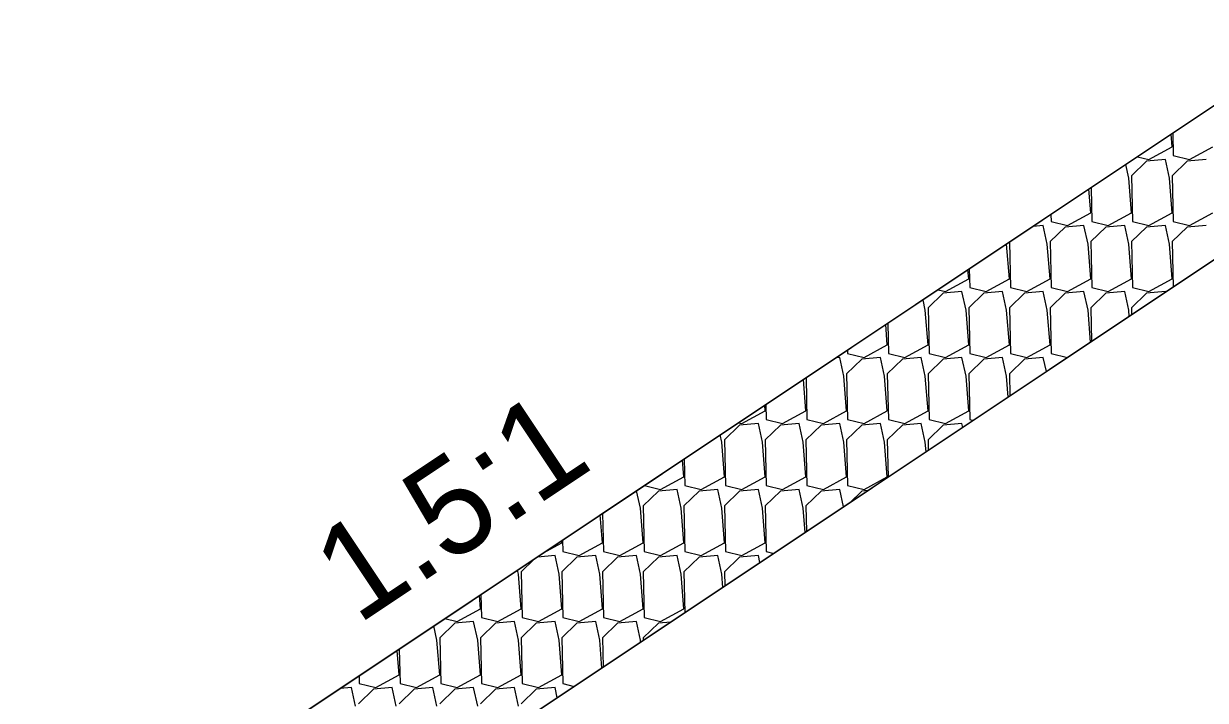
# Model space of a CAD drawing. Extents: x -26 to 4903, y -1010 to 9587.
# Drawn here: x 86.01 to 104.45, y 5010.51 to 5021.07 of the extents above; entities that cross this region are included whole.
import ezdxf

# ---------------------------------------------------------------- set-up
doc = ezdxf.new("R2010")
doc.units = 0
for name, color, linetype in [('Default', 7, 'Continuous'), ('Prop CMT Slope Grass', 7, 'Continuous'), ('Prop XS Class II Rip Rap Ditch Liner', 7, 'Continuous'), ('Prop XS Earthwork Shape', 7, 'Continuous'), ('Prop XS Side Slope Text', 7, 'Continuous')]:
    doc.layers.add(name, color=color, linetype=linetype)

msp = doc.modelspace()

# ---------------------------------------------------------------- linework, layer by layer
at = {"layer": 'Default'}
msp.add_line((106.5, 5021.066), (77.043, 5001.428), dxfattribs=at)
at = {"layer": 'Prop CMT Slope Grass'}
msp.add_line((110.001, 5020.996), (86.006, 5005), dxfattribs=at)
at = {"layer": 'Prop XS Class II Rip Rap Ditch Liner'}
for p, q in [((77.043, 5001.428), (106.5, 5021.066)), ((103.928, 5019.145), (103.912, 5019.341)), ((103.936, 5019.357), (103.943, 5019.011)), ((103.564, 5018.947), (103.928, 5019.145)), ((104.199, 5018.947), (104.563, 5019.145)), ((103.529, 5018.924), (103.293, 5018.695)), ((103.387, 5018.991), (103.564, 5018.947)), ((103.822, 5018.947), (103.529, 5018.924)), ((103.885, 5018.657), (103.822, 5018.947)), ((104.164, 5018.924), (103.928, 5018.695)), ((103.943, 5019.011), (104.199, 5018.947)), ((104.457, 5018.947), (104.164, 5018.924)), ((103.25, 5018.657), (103.204, 5018.869)), ((103.293, 5018.115), (103.25, 5018.657)), ((103.293, 5018.695), (103.308, 5017.982)), ((103.928, 5018.115), (103.885, 5018.657)), ((103.928, 5018.695), (103.943, 5017.982)), ((102.658, 5018.115), (102.629, 5018.486)), ((102.662, 5018.508), (102.673, 5017.982)), ((102.036, 5018.091), (102.038, 5017.982)), ((102.038, 5017.982), (102.294, 5017.917)), ((102.294, 5017.917), (102.658, 5018.115)), ((102.673, 5017.982), (102.929, 5017.917)), ((102.929, 5017.917), (103.293, 5018.115)), ((103.308, 5017.982), (103.564, 5017.917)), ((103.564, 5017.917), (103.928, 5018.115)), ((103.943, 5017.982), (104.199, 5017.917)), ((104.199, 5017.917), (104.563, 5018.115)), ((101.917, 5017.917), (101.757, 5017.905)), ((101.98, 5017.628), (101.917, 5017.917)), ((102.259, 5017.894), (102.023, 5017.666)), ((102.552, 5017.917), (102.259, 5017.894)), ((102.615, 5017.628), (102.552, 5017.917)), ((102.894, 5017.894), (102.658, 5017.666)), ((103.187, 5017.917), (102.894, 5017.894)), ((103.25, 5017.628), (103.187, 5017.917)), ((103.529, 5017.894), (103.293, 5017.666)), ((103.822, 5017.917), (103.529, 5017.894)), ((103.885, 5017.628), (103.822, 5017.917)), ((104.164, 5017.894), (103.928, 5017.666)), ((104.457, 5017.917), (104.164, 5017.894)), ((101.345, 5017.628), (101.345, 5017.63)), ((101.388, 5017.086), (101.345, 5017.628)), ((101.388, 5017.659), (101.403, 5016.952)), ((102.023, 5017.086), (101.98, 5017.628)), ((102.023, 5017.666), (102.038, 5016.952)), ((102.658, 5017.086), (102.615, 5017.628)), ((102.658, 5017.666), (102.673, 5016.952)), ((103.293, 5017.086), (103.25, 5017.628)), ((103.293, 5017.666), (103.308, 5016.952)), ((103.928, 5017.086), (103.885, 5017.628)), ((103.928, 5017.666), (103.943, 5016.958)), ((100.753, 5017.086), (100.742, 5017.228)), ((100.762, 5017.241), (100.769, 5016.952)), ((100.389, 5016.888), (100.753, 5017.086)), ((101.024, 5016.888), (101.388, 5017.086)), ((101.659, 5016.888), (102.023, 5017.086)), ((102.294, 5016.888), (102.658, 5017.086)), ((102.929, 5016.888), (103.293, 5017.086)), ((103.564, 5016.888), (103.928, 5017.086)), ((100.354, 5016.865), (100.118, 5016.636)), ((100.275, 5016.916), (100.389, 5016.888)), ((100.647, 5016.888), (100.354, 5016.865)), ((100.711, 5016.598), (100.647, 5016.888)), ((100.989, 5016.865), (100.753, 5016.636)), ((100.769, 5016.952), (101.024, 5016.888)), ((101.282, 5016.888), (100.989, 5016.865)), ((101.345, 5016.598), (101.282, 5016.888)), ((101.624, 5016.865), (101.388, 5016.636)), ((101.403, 5016.952), (101.659, 5016.888)), ((101.917, 5016.888), (101.624, 5016.865)), ((101.98, 5016.598), (101.917, 5016.888)), ((102.259, 5016.865), (102.023, 5016.636)), ((102.038, 5016.952), (102.294, 5016.888)), ((102.552, 5016.888), (102.259, 5016.865)), ((102.615, 5016.598), (102.552, 5016.888)), ((102.894, 5016.865), (102.658, 5016.636)), ((102.673, 5016.952), (102.929, 5016.888)), ((103.187, 5016.888), (102.894, 5016.865)), ((103.25, 5016.598), (103.187, 5016.888)), ((103.529, 5016.865), (103.293, 5016.636)), ((103.308, 5016.952), (103.564, 5016.888)), ((103.822, 5016.888), (103.529, 5016.865)), ((103.824, 5016.879), (103.822, 5016.888)), ((100.076, 5016.598), (100.04, 5016.76)), ((100.118, 5016.056), (100.076, 5016.598)), ((100.118, 5016.636), (100.134, 5015.923)), ((100.753, 5016.056), (100.711, 5016.598)), ((100.753, 5016.636), (100.769, 5015.923)), ((101.388, 5016.056), (101.345, 5016.598)), ((101.388, 5016.636), (101.403, 5015.923)), ((102.023, 5016.056), (101.98, 5016.598)), ((102.023, 5016.636), (102.038, 5015.923)), ((102.655, 5016.099), (102.615, 5016.598)), ((102.658, 5016.636), (102.669, 5016.109)), ((103.258, 5016.501), (103.25, 5016.598)), ((103.293, 5016.636), (103.295, 5016.526)), ((99.483, 5016.056), (99.458, 5016.372)), ((99.489, 5016.392), (99.499, 5015.923)), ((98.863, 5015.975), (98.864, 5015.923)), ((99.12, 5015.858), (99.483, 5016.056)), ((99.754, 5015.858), (100.118, 5016.056)), ((100.389, 5015.858), (100.753, 5016.056)), ((101.024, 5015.858), (101.388, 5016.056)), ((101.659, 5015.858), (102.023, 5016.056)), ((98.742, 5015.858), (98.68, 5015.853)), ((98.806, 5015.568), (98.742, 5015.858)), ((99.084, 5015.835), (98.848, 5015.606)), ((98.864, 5015.923), (99.12, 5015.858)), ((99.377, 5015.858), (99.084, 5015.835)), ((99.441, 5015.568), (99.377, 5015.858)), ((99.719, 5015.835), (99.483, 5015.606)), ((99.499, 5015.923), (99.754, 5015.858)), ((100.012, 5015.858), (99.719, 5015.835)), ((100.076, 5015.568), (100.012, 5015.858)), ((100.354, 5015.835), (100.118, 5015.606)), ((100.134, 5015.923), (100.389, 5015.858)), ((100.647, 5015.858), (100.354, 5015.835)), ((100.711, 5015.568), (100.647, 5015.858)), ((100.989, 5015.835), (100.753, 5015.606)), ((100.769, 5015.923), (101.024, 5015.858)), ((101.282, 5015.858), (100.989, 5015.835)), ((101.345, 5015.568), (101.282, 5015.858)), ((101.624, 5015.835), (101.388, 5015.606)), ((101.403, 5015.923), (101.659, 5015.858)), ((101.917, 5015.858), (101.624, 5015.835)), ((101.965, 5015.639), (101.917, 5015.858)), ((102.038, 5015.923), (102.293, 5015.858)), ((98.848, 5015.026), (98.806, 5015.568)), ((98.848, 5015.606), (98.864, 5014.893)), ((99.483, 5015.026), (99.441, 5015.568)), ((99.483, 5015.606), (99.499, 5014.893)), ((100.118, 5015.026), (100.076, 5015.568)), ((100.118, 5015.606), (100.134, 5014.893)), ((100.753, 5015.026), (100.711, 5015.568)), ((100.753, 5015.606), (100.769, 5014.893)), ((101.371, 5015.243), (101.345, 5015.568)), ((101.388, 5015.606), (101.396, 5015.26)), ((98.213, 5015.026), (98.175, 5015.516)), ((98.215, 5015.543), (98.229, 5014.893)), ((97.215, 5014.828), (97.578, 5015.026)), ((97.578, 5015.026), (97.572, 5015.114)), ((97.589, 5015.126), (97.594, 5014.893)), ((97.85, 5014.828), (98.213, 5015.026)), ((98.485, 5014.828), (98.848, 5015.026)), ((99.12, 5014.828), (99.483, 5015.026)), ((99.754, 5014.828), (100.118, 5015.026)), ((100.389, 5014.828), (100.753, 5015.026)), ((97.163, 5014.842), (97.215, 5014.828)), ((97.472, 5014.828), (97.179, 5014.805)), ((97.536, 5014.539), (97.472, 5014.828)), ((97.594, 5014.893), (97.85, 5014.828)), ((98.107, 5014.828), (97.814, 5014.805)), ((98.171, 5014.539), (98.107, 5014.828)), ((98.229, 5014.893), (98.485, 5014.828)), ((98.742, 5014.828), (98.449, 5014.805)), ((98.806, 5014.539), (98.742, 5014.828)), ((98.864, 5014.893), (99.12, 5014.828)), ((99.377, 5014.828), (99.084, 5014.805)), ((99.441, 5014.539), (99.377, 5014.828)), ((99.499, 5014.893), (99.754, 5014.828)), ((100.012, 5014.828), (99.719, 5014.805)), ((100.076, 5014.539), (100.012, 5014.828)), ((100.134, 5014.893), (100.389, 5014.828)), ((100.647, 5014.828), (100.354, 5014.805)), ((100.66, 5014.769), (100.647, 5014.828)), ((100.769, 5014.893), (100.824, 5014.879)), ((96.901, 5014.539), (96.876, 5014.651)), ((97.179, 5014.805), (96.944, 5014.577)), ((97.814, 5014.805), (97.578, 5014.577)), ((98.449, 5014.805), (98.213, 5014.577)), ((99.084, 5014.805), (98.848, 5014.577)), ((99.719, 5014.805), (99.483, 5014.577)), ((100.354, 5014.805), (100.118, 5014.577)), ((96.944, 5013.997), (96.901, 5014.539)), ((96.944, 5014.577), (96.959, 5013.863)), ((97.578, 5013.997), (97.536, 5014.539)), ((97.578, 5014.577), (97.594, 5013.863)), ((98.213, 5013.997), (98.171, 5014.539)), ((98.213, 5014.577), (98.229, 5013.863)), ((98.848, 5013.997), (98.806, 5014.539)), ((98.848, 5014.577), (98.864, 5013.863)), ((99.483, 5013.997), (99.441, 5014.539)), ((99.483, 5014.577), (99.496, 5013.993)), ((100.087, 5014.388), (100.076, 5014.539)), ((100.118, 5014.577), (100.122, 5014.411)), ((96.315, 5014.277), (96.324, 5013.863)), ((96.309, 5013.997), (96.288, 5014.258)), ((95.945, 5013.799), (96.309, 5013.997)), ((96.58, 5013.799), (96.944, 5013.997)), ((97.215, 5013.799), (97.578, 5013.997)), ((97.85, 5013.799), (98.213, 5013.997)), ((98.485, 5013.799), (98.848, 5013.997)), ((99.12, 5013.799), (99.483, 5013.997)), ((95.631, 5013.509), (95.571, 5013.781)), ((95.91, 5013.776), (95.674, 5013.547)), ((95.694, 5013.862), (95.945, 5013.799)), ((96.202, 5013.799), (95.91, 5013.776)), ((96.266, 5013.509), (96.202, 5013.799)), ((96.545, 5013.776), (96.309, 5013.547)), ((96.324, 5013.863), (96.58, 5013.799)), ((96.837, 5013.799), (96.545, 5013.776)), ((96.901, 5013.509), (96.837, 5013.799)), ((97.179, 5013.776), (96.944, 5013.547)), ((96.959, 5013.863), (97.215, 5013.799)), ((97.472, 5013.799), (97.179, 5013.776)), ((97.536, 5013.509), (97.472, 5013.799)), ((97.814, 5013.776), (97.578, 5013.547)), ((97.594, 5013.863), (97.85, 5013.799)), ((98.107, 5013.799), (97.814, 5013.776)), ((98.171, 5013.509), (98.107, 5013.799)), ((98.449, 5013.776), (98.213, 5013.547)), ((98.229, 5013.863), (98.485, 5013.799)), ((98.742, 5013.799), (98.449, 5013.776)), ((98.801, 5013.53), (98.742, 5013.799)), ((98.864, 5013.863), (99.12, 5013.799)), ((99.084, 5013.776), (98.896, 5013.594)), ((99.181, 5013.783), (99.084, 5013.776)), ((95.674, 5013.547), (95.689, 5012.834)), ((96.309, 5013.547), (96.324, 5012.834)), ((96.944, 5013.547), (96.959, 5012.834)), ((97.578, 5013.547), (97.594, 5012.834)), ((98.213, 5013.547), (98.222, 5013.144)), ((95.039, 5012.967), (95.004, 5013.403)), ((95.041, 5013.427), (95.054, 5012.834)), ((95.674, 5012.967), (95.631, 5013.509)), ((96.309, 5012.967), (96.266, 5013.509)), ((96.944, 5012.967), (96.901, 5013.509)), ((97.578, 5012.967), (97.536, 5013.509)), ((98.201, 5013.13), (98.171, 5013.509)), ((94.404, 5012.967), (94.401, 5013.001)), ((94.415, 5013.01), (94.419, 5012.834)), ((94.116, 5012.811), (94.404, 5012.967)), ((94.419, 5012.834), (94.675, 5012.769)), ((94.675, 5012.769), (95.039, 5012.967)), ((95.054, 5012.834), (95.31, 5012.769)), ((95.31, 5012.769), (95.674, 5012.967)), ((95.689, 5012.834), (95.945, 5012.769)), ((95.945, 5012.769), (96.309, 5012.967)), ((96.324, 5012.834), (96.58, 5012.769)), ((96.58, 5012.769), (96.944, 5012.967)), ((96.959, 5012.834), (97.215, 5012.769)), ((97.215, 5012.769), (97.578, 5012.967)), ((97.594, 5012.834), (97.712, 5012.804)), ((93.972, 5012.715), (93.769, 5012.518)), ((94.298, 5012.769), (94.022, 5012.747)), ((94.361, 5012.48), (94.298, 5012.769)), ((94.64, 5012.746), (94.404, 5012.518)), ((94.933, 5012.769), (94.64, 5012.746)), ((94.996, 5012.48), (94.933, 5012.769)), ((95.275, 5012.746), (95.039, 5012.518)), ((95.568, 5012.769), (95.275, 5012.746)), ((95.631, 5012.48), (95.568, 5012.769)), ((95.91, 5012.746), (95.674, 5012.518)), ((96.202, 5012.769), (95.91, 5012.746)), ((96.266, 5012.48), (96.202, 5012.769)), ((96.545, 5012.746), (96.309, 5012.518)), ((96.837, 5012.769), (96.545, 5012.746)), ((96.901, 5012.48), (96.837, 5012.769)), ((97.179, 5012.746), (96.944, 5012.518)), ((97.472, 5012.769), (97.179, 5012.746)), ((97.496, 5012.66), (97.472, 5012.769)), ((93.726, 5012.48), (93.713, 5012.542)), ((93.769, 5011.937), (93.726, 5012.48)), ((93.769, 5012.518), (93.784, 5011.804)), ((94.404, 5011.937), (94.361, 5012.48)), ((94.404, 5012.518), (94.419, 5011.804)), ((95.039, 5011.937), (94.996, 5012.48)), ((95.039, 5012.518), (95.054, 5011.804)), ((95.674, 5011.937), (95.631, 5012.48)), ((95.674, 5012.518), (95.689, 5011.804)), ((96.309, 5011.937), (96.266, 5012.48)), ((96.309, 5012.518), (96.322, 5011.878)), ((96.917, 5012.274), (96.901, 5012.48)), ((96.944, 5012.518), (96.948, 5012.295)), ((93.134, 5011.937), (93.118, 5012.145)), ((93.142, 5012.161), (93.149, 5011.804)), ((92.77, 5011.74), (93.134, 5011.937)), ((93.405, 5011.74), (93.769, 5011.937)), ((94.04, 5011.74), (94.404, 5011.937)), ((94.675, 5011.74), (95.039, 5011.937)), ((95.31, 5011.74), (95.674, 5011.937)), ((95.945, 5011.74), (96.309, 5011.937)), ((92.735, 5011.717), (92.499, 5011.488)), ((92.581, 5011.787), (92.77, 5011.74)), ((93.028, 5011.74), (92.735, 5011.717)), ((93.091, 5011.45), (93.028, 5011.74)), ((93.37, 5011.717), (93.134, 5011.488)), ((93.149, 5011.804), (93.405, 5011.74)), ((93.663, 5011.74), (93.37, 5011.717)), ((93.726, 5011.45), (93.663, 5011.74)), ((94.005, 5011.717), (93.769, 5011.488)), ((93.784, 5011.804), (94.04, 5011.74)), ((94.298, 5011.74), (94.005, 5011.717)), ((94.361, 5011.45), (94.298, 5011.74)), ((94.64, 5011.717), (94.404, 5011.488)), ((94.419, 5011.804), (94.675, 5011.74)), ((94.933, 5011.74), (94.64, 5011.717)), ((94.996, 5011.45), (94.933, 5011.74)), ((95.275, 5011.717), (95.039, 5011.488)), ((95.054, 5011.804), (95.31, 5011.74)), ((95.568, 5011.74), (95.275, 5011.717)), ((95.631, 5011.45), (95.568, 5011.74)), ((95.91, 5011.717), (95.674, 5011.488)), ((95.689, 5011.804), (95.945, 5011.74)), ((96.104, 5011.732), (95.91, 5011.717)), ((92.456, 5011.45), (92.408, 5011.672)), ((92.499, 5010.908), (92.456, 5011.45)), ((92.499, 5011.488), (92.514, 5010.774)), ((93.134, 5010.908), (93.091, 5011.45)), ((93.134, 5011.488), (93.149, 5010.774)), ((93.769, 5010.908), (93.726, 5011.45)), ((93.769, 5011.488), (93.784, 5010.774)), ((94.404, 5010.908), (94.361, 5011.45)), ((94.404, 5011.488), (94.419, 5010.774)), ((95.03, 5011.016), (94.996, 5011.45)), ((95.039, 5011.488), (95.049, 5011.029)), ((95.634, 5011.418), (95.631, 5011.45)), ((95.674, 5011.488), (95.675, 5011.446)), ((91.864, 5010.908), (91.834, 5011.289)), ((91.868, 5011.312), (91.879, 5010.774)), ((91.242, 5010.894), (91.244, 5010.774)), ((91.244, 5010.774), (91.5, 5010.71)), ((91.5, 5010.71), (91.864, 5010.908)), ((91.879, 5010.774), (92.135, 5010.71)), ((92.135, 5010.71), (92.499, 5010.908)), ((92.514, 5010.774), (92.77, 5010.71)), ((92.77, 5010.71), (93.134, 5010.908)), ((93.149, 5010.774), (93.405, 5010.71)), ((93.405, 5010.71), (93.769, 5010.908)), ((93.784, 5010.774), (94.04, 5010.71)), ((94.04, 5010.71), (94.404, 5010.908)), ((94.419, 5010.774), (94.599, 5010.729)), ((91.123, 5010.71), (90.944, 5010.696)), ((91.186, 5010.42), (91.123, 5010.71)), ((91.465, 5010.687), (91.229, 5010.458)), ((91.758, 5010.71), (91.465, 5010.687)), ((91.821, 5010.42), (91.758, 5010.71)), ((92.1, 5010.687), (91.864, 5010.458)), ((92.393, 5010.71), (92.1, 5010.687)), ((92.456, 5010.42), (92.393, 5010.71)), ((92.735, 5010.687), (92.499, 5010.458)), ((93.028, 5010.71), (92.735, 5010.687)), ((93.091, 5010.42), (93.028, 5010.71)), ((93.37, 5010.687), (93.134, 5010.458)), ((93.663, 5010.71), (93.37, 5010.687)), ((93.726, 5010.42), (93.663, 5010.71)), ((94.005, 5010.687), (93.769, 5010.458)), ((94.298, 5010.71), (94.005, 5010.687)), ((94.332, 5010.551), (94.298, 5010.71))]:
    msp.add_line(p, q, dxfattribs=at)
at = {"layer": 'Prop XS Earthwork Shape'}
msp.add_lwpolyline([(123.257, 5020.731), (110.001, 5020.996), (86.006, 5005), (104.436, 5005), (109.032, 5006.537), (110.708, 5007.103), (111.08, 5007.184), (111.406, 5007.259), (112.041, 5007.42), (112.454, 5007.677), (114.126, 5009.01), (115.299, 5009.933), (119.979, 5013.606), (124.352, 5016.647), (126.885, 5018.359), (132.523, 5019.269), (134.333, 5019.565), (128, 5019.406), (124.665, 5019.323)], close=True, dxfattribs=at)

# ---------------------------------------------------------------- texts
at = {"layer": 'Prop XS Side Slope Text'}
msp.add_text('1.5:1', height=1.5, rotation=33.6901, dxfattribs=at).set_placement((91.217, 5011.68))

doc.saveas('drawing.dxf')
